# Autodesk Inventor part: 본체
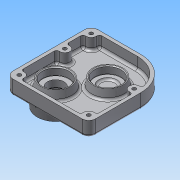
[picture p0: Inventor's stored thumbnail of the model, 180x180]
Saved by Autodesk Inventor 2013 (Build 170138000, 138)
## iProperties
Created: 2015-11
Part Number: 본체
Material: 알루미늄 6061
Document SubType Name: Modeling
Designer: Administrator
Density: 2.71 g/cm^3
Mass: 247.293 g
Surface Area: 390.248 cm^2
Volume: 91.2522 cm^3
Author: Administrator
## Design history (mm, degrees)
sketch "스케치1"
  geometry: L1 (-60, 40)-(-60, -63); L2 (-60, -63)-(40, -63); L3 (40, -63)-(40, 0); L4 (0, 40)-(-60, 40); A1 r 40 centre (0, 0) between (40, 0) and (0, 40); 1 further point
  constraints: 8 end point, 2 coincident, 2 parallel, 2 point on circle, 2 tangent, 1 centre point, 1 perpendicular, 1 vertical
  dimensions: "d0" = 103 distance between parallel lines of L2 L4; "d3" = 100 distance of L1.end L2.end; "d135" = 40 radius of A1
extrude "돌출1" new body sketch "스케치1" distance "d4" = 4; taper "d5" = 0 deg
fillet "모깎기1" dims "d6" = 8
sketch "스케치4"
  geometry: L1 (40, -55)-(40, 0) reference; L2 (0, 40)-(-52, 40) reference; L3 (-60, 32)-(-60, -55) reference; L4 (-52, -63)-(32, -63) reference; L5 (-47.528, 36)-(0, 36); L6 (36, -4.472)-(36, -50.528); L7 (27.528, -59)-(-47.528, -59); L8 (-56, -50.528)-(-56, -4.472); L9 (-56, 4.472)-(-56, 27.528); A1 r 8 centre (32, -55) between (32, -63) and (40, -55) reference; A2 r 40 centre (0, 0) between (40, 0) and (0, 40) reference; A3 r 8 centre (-52, 32) between (-52, 40) and (-60, 32) reference; A4 r 8 centre (-52, -55) between (-60, -55) and (-52, -63) reference; A5 r 36 centre (0, 0) between (35.688, 4.733) and (0, 36); A6 r 6 centre (-52, 32) between (-56, 27.528) and (-47.528, 36); A7 r 6 centre (-52, -55) between (-47.528, -59) and (-56, -50.528); A8 r 6 centre (-52, 0) between (-56, -4.472) and (-56, 4.472); A9 r 6 centre (32, 0) between (35.688, 4.733) and (36, -4.472); A10 r 6 centre (32, -55) between (36, -50.528) and (27.528, -59)
  constraints: 12 point on circle, 10 end point, 6 centre point, 4 coincident, 2 concentric, 2 horizontal alignment, 2 vertical alignment
  dimensions: "d17" = 4 distance between parallel lines of L2 L5; "d18" = 4 distance between parallel lines of L4 L7; "d20" = 12 diameter of A6; "d21" = 12 diameter of A7; "d22" = 12 diameter of A10; "d23" = 12 diameter of A9; "d24" = 12 diameter of A8; "d25" = 84 distance of A9.centre A8.centre; "d26" = 36 radius of A5; "d28" = 4 distance between parallel lines of L1 L6; "d29" = 4 distance between parallel lines of L3 L8; "d30" = 4 distance between parallel lines of L3 L9
extrude "돌출2" join sketch "스케치4" distance "d31" = 14; taper "d32" = 0 deg
sketch "스케치5"
  geometry: C1 r 20 at (0, 0); A1 r 36 centre (0, 0) between (35.688, 4.733) and (0, 36) reference
  constraints: 2 coincident, 1 centre point
  dimensions: "d136" = 40 diameter of C1
extrude "돌출3" join sketch "스케치5" distance "d35" = 11; taper "d36" = -10 deg
sketch "스케치7"
  geometry: C1 r 18.06 at (0, 0) reference; C2 r 16 at (0, 0)
  constraints: 2 coincident, 1 centre point
  dimensions: "d44" = 32 diameter of C2
extrude "돌출4" cut sketch "스케치7" distance "d46" = 9; taper "d47" = 0 deg
sketch "스케치8"
  geometry: C1 r 16 at (0, 0) reference; C2 r 11 at (0, 0)
  constraints: 1 centre point, 1 coincident
  dimensions: "d48" = 22 diameter of C2
extrude "돌출5" cut sketch "스케치8" distance "d50" = 2; taper "d51" = 0 deg
sketch "스케치10"
  geometry: L1 (52, -63)-(-32, -63) reference; L2 (60, 32)-(60, -55) reference; C1 r 25 at (30, -33)
  constraints: 1 centre point
  dimensions: "d55" = 30 distance from line of C1.centre L2; "d56" = 30 distance from line of L1 C1.centre; "d57" = 50 diameter of C1
extrude "돌출6" join sketch "스케치10" distance "d58" = 15; taper "d59" = -10 deg
sketch "스케치11"
  geometry: C1 r 22.355 at (0, 0) reference; 2 further points
  constraints: 1 coincident
hole "구멍2" sketch "스케치11" at (0, 0) diameter "d60" = 24; stored, may be unused: countersink angle "d64" = 90 deg, drill point angle "d66" = 0 deg; dims "d61" = 6, "d62" = 28, "d63" = 11, "d65" = 13
sketch "스케치13"
  geometry: L1 (-60, 32)-(-60, -55) reference; L2 (-52, -63)-(32, -63) reference; C1 r 20 at (-30, -33)
  constraints: 1 centre point
  dimensions: "d71" = 30 distance from line of L1 C1.centre; "d72" = 30 distance from line of C1.centre L2; "d73" = 40 diameter of C1
extrude "돌출8" join sketch "스케치13" distance "d74" = 11; taper "d75" = -10 deg
sketch "스케치16"
  geometry: C1 r 18.06 at (0, 0) reference; 2 further points
  constraints: 1 coincident
hole "구멍3" sketch "스케치16" at (0, 0) diameter "d79" = 20; stored, may be unused: countersink angle "d83" = 90 deg, drill point angle "d85" = 0 deg; dims "d80" = 6, "d81" = 32, "d82" = 9, "d84" = 20
fillet "모깎기2" dims "d107" = 3
fillet "모깎기3" dims "d108" = 3
sketch "스케치21"
  geometry: L1 (-4.887, 23.602)-(44.887, 23.602); L2 (44.887, 23.602)-(44.887, 16.398); L3 (44.887, 16.398)-(-4.887, 16.398); L4 (-4.887, 16.398)-(-4.887, 23.602); L5 (60, -27.689)-(60, 32) reference; L6 (52, 40)-(0, 40) reference; 2 further points
  constraints: 1 midpoint, 1 vertical alignment, 2 other
  dimensions: "d138" = 20 distance from line of point (20, 20) L6; "d139" = 40 distance from line of L5 point (20, 20)
feature "엠보싱1" sketch "스케치21" dims "d111" = 0.5, "d112" = 0
sketch "스케치22"
  geometry: C1 r 14 at (0, 0) reference; 2 further points
  constraints: 1 vertical alignment
  dimensions: "d113" = 18 distance of C1.centre point (0, 18)
hole "구멍4" sketch "스케치22" at (0, 18) diameter "d114" = 2.459; stored, may be unused: countersink angle "d118" = 90 deg, drill point angle "d120" = 118 deg; dims "d115" = 8, "d116" = 32, "d117" = 9, "d119" = 10
chamfer "모따기1" distance "d124" = 1; stored, may be unused: second distance "d125" = 2, angle "d126" = 45 deg
fillet "모깎기4" dims "d127" = 0.3
sketch "스케치26"
  geometry: L1 (42.787, 19.996)-(41.191, 19.996) reference; L2 (41.191, 19.996)-(41.191, 20.452) reference; L3 (41.191, 20.452)-(42.787, 20.452) reference; L4 (42.787, 20.452)-(42.787, 23.545) reference; L5 (42.787, 23.545)-(43.178, 23.545) reference; L6 (43.341, 23.228)-(43.341, 16.422) reference; L7 (43.341, 16.422)-(42.787, 16.422) reference; L8 (42.787, 16.422)-(42.787, 19.996) reference; L9 (3.27, 20.777)-(3.27, 20.305) reference; L10 (3.27, 20.305)-(1.927, 20.305) reference; L11 (1.927, 20.305)-(1.927, 18.213) reference; L12 (1.927, 18.213)-(1.357, 18.213) reference; L13 (1.357, 18.213)-(1.357, 23.602) reference; L14 (1.357, 23.602)-(1.723, 23.602) reference; L15 (1.927, 23.285)-(1.927, 20.777) reference; L16 (1.927, 20.777)-(3.27, 20.777) reference; L17 (2.187, 17.073)-(2.187, 16.617) reference; L18 (2.187, 16.617)-(-3.031, 16.617) reference; L19 (-3.031, 16.617)-(-3.031, 18.571) reference; L20 (-3.031, 18.571)-(-2.608, 18.571) reference; L21 (-2.478, 18.311)-(-2.478, 17.073) reference; L22 (-2.478, 17.073)-(2.187, 17.073) reference; L23 (-0.849, 22.91)-(-2.624, 22.91) reference; L24 (-2.624, 22.91)-(-2.624, 23.334) reference; L25 (-2.624, 23.334)-(-0.849, 23.334) reference; L26 (-0.849, 23.334)-(-0.849, 22.91) reference; L27 (-4.057, 21.942)-(-4.057, 22.365) reference; L28 (-4.057, 22.365)-(0.461, 22.365) reference; L29 (0.461, 22.365)-(0.461, 21.942) reference; L30 (0.461, 21.942)-(-4.057, 21.942) reference; L31 (16.499, 16.862)-(15.832, 18.693) reference; L32 (15.832, 18.693)-(13.129, 18.693) reference; L33 (13.129, 18.693)-(12.445, 16.862) reference; L34 (12.445, 16.862)-(11.867, 16.862) reference; L35 (11.867, 16.862)-(14.147, 22.862) reference; L36 (14.147, 22.862)-(14.798, 22.862) reference; L37 (14.798, 22.862)-(17.077, 16.862) reference; L38 (17.077, 16.862)-(16.499, 16.862) reference; L39 (14.464, 22.275)-(13.316, 19.19) reference; L40 (13.316, 19.19)-(15.636, 19.19) reference; L41 (15.636, 19.19)-(14.464, 22.275) reference; L42 (7.886, 18.978)-(10.06, 18.978) reference; L43 (10.06, 18.978)-(10.06, 16.43) reference; L44 (10.06, 16.43)-(9.506, 16.43) reference; L45 (9.506, 16.43)-(9.506, 18.531) reference; L46 (9.506, 18.531)-(4.906, 18.531) reference; L47 (4.906, 18.531)-(4.906, 18.978) reference; L48 (4.906, 18.978)-(7.341, 18.978) reference; L49 (7.341, 18.978)-(7.341, 20.444) reference; L50 (7.341, 20.444)-(4.027, 20.444) reference; L51 (4.027, 20.444)-(4.027, 20.891) reference; L52 (4.027, 20.891)-(9.27, 20.891) reference; L53 (9.612, 22.894)-(5.045, 22.894) reference; L54 (5.045, 22.894)-(5.045, 23.35) reference; L55 (5.045, 23.35)-(10.19, 23.35) reference; L56 (9.864, 20.891)-(11.232, 20.891) reference; L57 (11.232, 20.891)-(11.232, 20.444) reference; L58 (11.232, 20.444)-(7.886, 20.444) reference; L59 (7.886, 20.444)-(7.886, 18.978) reference; L60 (21.832, 22.862)-(21.832, 22.365) reference; L61 (21.832, 22.365)-(19.959, 22.365) reference; L62 (19.959, 22.365)-(19.959, 16.862) reference; L63 (19.959, 16.862)-(19.414, 16.862) reference; L64 (19.414, 16.862)-(19.414, 22.365) reference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; C1 r 10 at (30, -33) reference; A1 r 5 centre (52, 32) between (57, 32) and (52, 37) reference; A2 r 5 centre (52, -55) between (52, -60) and (57, -55) reference; A3 r 27.517 centre (30, -33) between (35.311, -60) and (57, -38.311) reference; A4 r 37 centre (0, 0) between (0, 37) and (-37, 0) reference; A5 r 5 centre (-32, -55) between (-37, -55) and (-32, -60) reference; A6 r 27.517 centre (30, -33) between (57, -27.689) and (24.689, -60) reference; A7 r 6 centre (-32, 0) between (-32.667, -5.963) and (-31.833, 5.998) reference; A8 r 6 centre (52, 0) between (52.667, 5.963) and (52.667, -5.963) reference; 66 further points
  constraints: 5 coincident, 1 horizontal alignment, 1 vertical alignment, 76 other
hole "구멍5" sketch "스케치26" at (-32, 0), (52, 32), (52, 0), (52, -55), (-32, -55) diameter "d128" = 4.5; stored, may be unused: countersink angle "d132" = 90 deg, drill point angle "d134" = 118 deg; dims "d129" = 6, "d130" = 8, "d131" = 4.4, "d133" = 8
node "솔리드1"
pattern_circular "원형 패턴1" dims angle "d122" = 360 deg
node "절단 모서리 투영3"
other parameters: "d19" = 4
